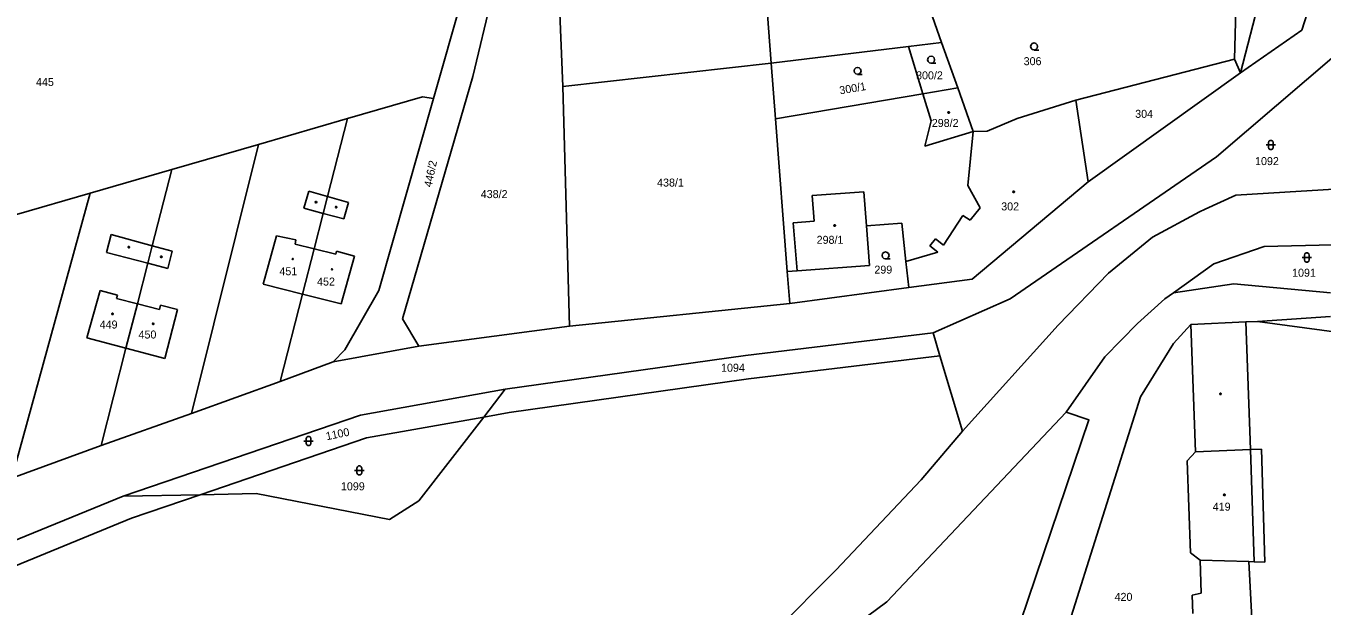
# Model space of a CAD drawing. Extents: x -812394 to -807601, y -1013097 to -1009266.
# Drawn here: x -811273.1 to -810997.7, y -1011712.3 to -1011589.1 of the extents above; entities that cross this region are included whole.
import ezdxf

# ---------------------------------------------------------------- set-up
doc = ezdxf.new("R2010")
doc.units = 0
for name, color, linetype in [('Default', 7, 'Continuous'), ('KN_HRANICE', 7, 'Continuous'), ('KN_KULTURY', 7, 'Continuous'), ('KN_PARCELY', 7, 'Continuous'), ('KN_SLUCKY', 7, 'Continuous')]:
    doc.layers.add(name, color=color, linetype=linetype)

# ---------------------------------------------------------------- blocks, each defined once
blk = doc.blocks.new('304')
at = {"layer": 'Default'}
blk.add_lwpolyline([(0, 0), (-0.38, 0.1), (-0.65, 0.37), (-0.75, 0.74), (-0.65, 1.11), (-0.38, 1.38), (-0.01, 1.48), (0.36, 1.38), (0.63, 1.11), (0.73, 0.73), (0.63, 0.35), (0.36, 0.08), (-0.02, -0.02), (0.98, -0.02)], dxfattribs=at)
blk = doc.blocks.new('316')
at = {"layer": 'Default'}
for points in [[(-1, 1), (0.27, 1), (1, 1)], [(-0.5, 1.5), (-0.4, 1.79), (-0.15, 1.97), (0.16, 1.97), (0.41, 1.79), (0.51, 1.5), (0.51, 0.5), (0.41, 0.21), (0.16, 0.03), (-0.15, 0.03), (-0.4, 0.21), (-0.5, 0.5), (-0.5, 1.5)]]:
    blk.add_lwpolyline(points, dxfattribs=at)
blk = doc.blocks.new('NAHRADNI_SYMBOL')
at = {"layer": 'Default'}
blk.add_lwpolyline([(0.09, 0.15), (0.18, 0), (0.09, -0.15), (-0.09, -0.15), (-0.18, 0), (-0.09, 0.15), (0.09, 0.15)], dxfattribs=at)
blk = doc.blocks.new('402')
at = {"layer": 'Default'}
blk.add_lwpolyline([(0.09, 0.15), (0.18, 0), (0.09, -0.15), (-0.09, -0.15), (-0.18, 0), (-0.09, 0.15), (0.09, 0.15)], dxfattribs=at)

msp = doc.modelspace()

# ---------------------------------------------------------------- linework, layer by layer
at = {"layer": 'KN_HRANICE'}
for p, q in [((-811178.18, -1011599.83), (-811166.46, -1011550.55)), ((-811078.55, -1011592.58), (-811086.24, -1011570.61)), ((-811008.1, -1011572.3), (-811015.03, -1011599.04)), ((-811114.74, -1011597.01), (-811116.42, -1011574.14)), ((-811186.53, -1011604.51), (-811179.22, -1011578.9)), ((-811159.98, -1011578.81), (-811159.05, -1011601.95)), ((-811001.99, -1011589.96), (-810998.41, -1011578.57)), ((-811016.02, -1011585.65), (-811016.27, -1011596.11)), ((-811015.03, -1011599.04), (-811001.99, -1011589.96)), ((-811114.74, -1011597.01), (-811085.57, -1011593.44)), ((-811085.57, -1011593.44), (-811078.55, -1011592.58)), ((-811082.51, -1011603.49), (-811085.57, -1011593.44)), ((-811078.55, -1011592.58), (-811075.12, -1011602.24)), ((-811159.05, -1011601.95), (-811114.74, -1011597.01)), ((-811113.84, -1011608.78), (-811114.74, -1011597.01)), ((-811049.99, -1011604.85), (-811016.27, -1011596.11)), ((-811020.14, -1011616.85), (-810994.59, -1011595.07)), ((-811015.03, -1011599.04), (-811016.27, -1011596.11)), ((-811193.09, -1011651.29), (-811178.18, -1011599.83)), ((-811047.37, -1011622.22), (-811015.03, -1011599.04)), ((-811159.05, -1011601.95), (-811157.58, -1011652.84)), ((-811075.12, -1011602.24), (-811082.51, -1011603.49)), ((-811075.12, -1011602.24), (-811071.83, -1011611.51)), ((-811204.79, -1011608.77), (-811188.82, -1011604.14)), ((-811198.15, -1011645.26), (-811186.53, -1011604.51)), ((-811188.82, -1011604.14), (-811186.53, -1011604.51)), ((-811082.51, -1011603.49), (-811113.84, -1011608.78)), ((-811080.76, -1011609.22), (-811082.51, -1011603.49)), ((-811062.46, -1011608.77), (-811049.99, -1011604.85)), ((-811047.37, -1011622.22), (-811049.99, -1011604.85)), ((-811223.68, -1011614.25), (-811204.79, -1011608.77)), ((-811209.02, -1011625.33), (-811204.79, -1011608.77)), ((-811111.34, -1011641.25), (-811113.84, -1011608.78)), ((-811082.09, -1011614.65), (-811080.76, -1011609.22)), ((-811068.83, -1011611.45), (-811062.46, -1011608.77)), ((-811071.83, -1011611.51), (-811082.09, -1011614.65)), ((-811072.96, -1011622.96), (-811071.83, -1011611.51)), ((-811071.83, -1011611.51), (-811068.83, -1011611.45)), ((-811242.11, -1011619.59), (-811223.68, -1011614.25)), ((-811237.94, -1011671.39), (-811223.68, -1011614.25)), ((-811063.97, -1011647.03), (-811020.14, -1011616.85)), ((-811259.45, -1011624.61), (-811242.11, -1011619.59)), ((-811246.26, -1011635.77), (-811242.11, -1011619.59)), ((-811276.13, -1011685.2), (-811259.45, -1011624.61)), ((-811275.14, -1011629.16), (-811259.45, -1011624.61)), ((-811070.33, -1011627.71), (-811072.96, -1011622.96)), ((-811072.01, -1011642.87), (-811047.37, -1011622.22)), ((-811209.93, -1011628.91), (-811209.02, -1011625.33)), ((-811211.85, -1011636.43), (-811209.93, -1011628.91)), ((-811074.03, -1011629.35), (-811078.1, -1011635.68)), ((-811072.48, -1011630.33), (-811074.03, -1011629.35)), ((-811070.33, -1011627.71), (-811072.48, -1011630.33)), ((-811033.74, -1011633.95), (-811023.75, -1011628.6)), ((-811023.75, -1011628.6), (-811022.52, -1011628.03)), ((-811094.5, -1011631.56), (-811086.99, -1011630.95)), ((-811094.5, -1011631.56), (-811093.86, -1011639.95)), ((-811086.99, -1011630.95), (-811086.11, -1011639.13)), ((-811247.2, -1011639.45), (-811246.26, -1011635.77)), ((-811079.86, -1011634.34), (-811081.05, -1011635.82)), ((-811081.05, -1011635.82), (-811079.35, -1011637.16)), ((-811078.1, -1011635.68), (-811079.86, -1011634.34)), ((-811043.08, -1011641.62), (-811033.74, -1011633.95)), ((-811214.31, -1011646.05), (-811211.85, -1011636.43)), ((-811086.11, -1011639.13), (-811079.35, -1011637.16)), ((-811249.43, -1011648.14), (-811247.2, -1011639.45)), ((-811109.22, -1011641.09), (-811111.34, -1011641.25)), ((-811110.82, -1011648.06), (-811111.34, -1011641.25)), ((-811093.86, -1011639.95), (-811109.22, -1011641.09)), ((-811086.11, -1011639.13), (-811085.52, -1011644.68)), ((-811085.52, -1011644.68), (-811072.01, -1011642.87)), ((-811053.75, -1011652.65), (-811043.08, -1011641.62)), ((-811016.44, -1011643.9), (-811029.29, -1011645.78)), ((-810995.89, -1011645.77), (-811016.44, -1011643.9)), ((-811219.05, -1011664.64), (-811214.31, -1011646.05)), ((-811205.32, -1011657.9), (-811198.15, -1011645.26)), ((-811110.82, -1011648.06), (-811085.52, -1011644.68)), ((-811251.85, -1011657.56), (-811249.43, -1011648.14)), ((-811110.82, -1011648.06), (-811157.58, -1011652.84)), ((-811080.33, -1011654.28), (-811063.97, -1011647.03)), ((-811189.59, -1011657.14), (-811193.09, -1011651.29)), ((-811013.86, -1011651.97), (-811025.55, -1011652.51)), ((-811011.38, -1011651.85), (-811013.86, -1011651.97)), ((-811011.38, -1011651.85), (-810995.89, -1011650.79)), ((-810971.7, -1011657.24), (-811011.38, -1011651.85)), ((-811189.59, -1011657.14), (-811157.58, -1011652.84)), ((-811120.19, -1011659.13), (-811080.33, -1011654.28)), ((-811080.33, -1011654.28), (-811078.89, -1011659.14)), ((-811074.13, -1011675.17), (-811053.75, -1011652.65)), ((-811025.55, -1011652.51), (-811029.28, -1011656.56)), ((-811024.55, -1011679.56), (-811025.55, -1011652.51)), ((-811257.15, -1011678.25), (-811251.85, -1011657.56)), ((-811207.83, -1011660.48), (-811189.59, -1011657.14)), ((-811207.83, -1011660.48), (-811205.32, -1011657.9)), ((-811029.28, -1011656.56), (-811036.27, -1011667.85)), ((-811219.05, -1011664.64), (-811207.83, -1011660.48)), ((-811171.25, -1011666.28), (-811120.19, -1011659.13)), ((-811078.89, -1011659.14), (-811119.54, -1011664.09)), ((-811074.13, -1011675.17), (-811078.89, -1011659.14)), ((-811237.94, -1011671.39), (-811219.05, -1011664.64)), ((-811119.54, -1011664.09), (-811170.46, -1011671.22)), ((-811202.01, -1011671.78), (-811171.25, -1011666.28)), ((-811171.25, -1011666.28), (-811175.83, -1011672.18)), ((-811036.27, -1011667.85), (-811058.25, -1011737.49)), ((-811257.15, -1011678.25), (-811237.94, -1011671.39)), ((-811170.46, -1011671.22), (-811175.83, -1011672.18)), ((-811252.46, -1011689.01), (-811202.01, -1011671.78)), ((-811175.83, -1011672.18), (-811200.75, -1011676.63)), ((-811189.64, -1011689.98), (-811175.83, -1011672.18)), ((-811200.75, -1011676.63), (-811236.06, -1011688.69)), ((-811082.88, -1011685.55), (-811074.13, -1011675.17)), ((-811276.13, -1011685.2), (-811257.15, -1011678.25)), ((-811026.38, -1011681.48), (-811024.55, -1011679.56)), ((-811024.55, -1011679.56), (-811012.93, -1011679.1)), ((-811012.93, -1011679.1), (-811010.59, -1011679.01)), ((-811009.86, -1011703), (-811010.59, -1011679.01)), ((-811025.62, -1011701.03), (-811026.38, -1011681.48)), ((-811101.04, -1011704.72), (-811082.88, -1011685.55)), ((-811305.52, -1011710.63), (-811252.46, -1011689.01)), ((-811236.06, -1011688.69), (-811252.46, -1011689.01)), ((-811236.06, -1011688.69), (-811250.71, -1011693.69)), ((-811236.06, -1011688.69), (-811224.18, -1011688.46)), ((-811224.18, -1011688.46), (-811195.82, -1011693.94)), ((-811195.82, -1011693.94), (-811189.64, -1011689.98)), ((-811250.71, -1011693.69), (-811375.13, -1011744.58)), ((-811025.62, -1011701.03), (-811023.6, -1011702.59)), ((-811113.97, -1011717.72), (-811101.04, -1011704.72)), ((-811023.6, -1011702.59), (-811023.35, -1011709.59)), ((-811023.6, -1011702.59), (-811013.26, -1011702.91)), ((-811013.26, -1011702.91), (-811012.11, -1011702.94)), ((-811012.11, -1011702.94), (-811009.86, -1011703)), ((-811023.35, -1011709.59), (-811025.3, -1011710.01)), ((-811025.3, -1011710.01), (-811025.13, -1011713.95))]:
    msp.add_line(p, q, dxfattribs=at)
for points in [[(-811005.6, -1011624.4), (-811016.01, -1011625.04), (-811022.52, -1011628.03)], [(-810982.75, -1011623.07), (-810983.49, -1011623.04), (-811005.6, -1011624.4)], [(-811029.29, -1011645.78), (-811020.71, -1011639.62), (-811010, -1011635.94), (-810983.72, -1011635.29), (-810982.94, -1011635.34)], [(-811052.04, -1011671.11), (-811043.88, -1011659.38), (-811036.94, -1011652.27), (-811031.09, -1011647.08), (-811029.29, -1011645.78)], [(-811123.04, -1011735.83), (-811090.17, -1011711.42), (-811052.04, -1011671.11)], [(-811074.63, -1011753.78), (-811047.22, -1011672.77), (-811052.04, -1011671.11)]]:
    msp.add_lwpolyline(points, dxfattribs=at)
at = {"layer": 'KN_SLUCKY'}
for p, q in [((-811212.97, -1011624.2), (-811214.03, -1011627.79)), ((-811209.02, -1011625.33), (-811212.97, -1011624.2)), ((-811106.05, -1011625.09), (-811095.06, -1011624.33)), ((-811095.06, -1011624.33), (-811094.5, -1011631.56)), ((-811204.58, -1011626.6), (-811209.02, -1011625.33)), ((-811205.58, -1011630.09), (-811204.58, -1011626.6)), ((-811105.59, -1011630.56), (-811106.05, -1011625.09)), ((-811214.03, -1011627.79), (-811209.93, -1011628.91)), ((-811209.93, -1011628.91), (-811205.58, -1011630.09)), ((-811110.07, -1011630.94), (-811105.59, -1011630.56)), ((-811109.22, -1011641.09), (-811110.07, -1011630.94)), ((-811255.01, -1011633.38), (-811256.02, -1011637.19)), ((-811246.26, -1011635.77), (-811255.01, -1011633.38)), ((-811242.03, -1011636.92), (-811246.26, -1011635.77)), ((-811219.86, -1011633.69), (-811222.71, -1011643.91)), ((-811215.73, -1011634.51), (-811219.86, -1011633.69)), ((-811215.87, -1011635.44), (-811215.73, -1011634.51)), ((-811211.85, -1011636.43), (-811215.87, -1011635.44)), ((-811247.2, -1011639.45), (-811256.02, -1011637.19)), ((-811242.99, -1011640.61), (-811242.03, -1011636.92)), ((-811207.26, -1011637.55), (-811211.85, -1011636.43)), ((-811207.08, -1011636.91), (-811207.26, -1011637.55)), ((-811203.29, -1011637.97), (-811207.08, -1011636.91)), ((-811206.13, -1011648.13), (-811203.29, -1011637.97)), ((-811247.2, -1011639.45), (-811242.99, -1011640.61)), ((-811222.71, -1011643.91), (-811214.31, -1011646.05)), ((-811257.36, -1011645.28), (-811260.18, -1011655.38)), ((-811253.64, -1011646.25), (-811257.36, -1011645.28)), ((-811253.83, -1011646.99), (-811253.64, -1011646.25)), ((-811214.31, -1011646.05), (-811206.13, -1011648.13)), ((-811249.43, -1011648.14), (-811253.83, -1011646.99)), ((-811244.72, -1011649.36), (-811249.43, -1011648.14)), ((-811244.48, -1011648.43), (-811244.72, -1011649.36)), ((-811240.89, -1011649.36), (-811244.48, -1011648.43)), ((-811243.58, -1011659.72), (-811240.89, -1011649.36)), ((-811012.93, -1011679.1), (-811013.86, -1011651.97)), ((-811260.18, -1011655.38), (-811251.85, -1011657.56)), ((-811251.85, -1011657.56), (-811243.58, -1011659.72)), ((-811012.11, -1011702.94), (-811012.93, -1011679.1)), ((-811013.26, -1011702.91), (-811012.49, -1011717.69))]:
    msp.add_line(p, q, dxfattribs=at)

# ---------------------------------------------------------------- block references
at = {"layer": 'KN_KULTURY'}
for name, p in [('304', (-811058.88, -1011594.17)), ('304', (-811080.75, -1011596.98)), ('304', (-811096.38, -1011599.35)), ('NAHRADNI_SYMBOL', (-811077.02, -1011607.45)), ('316', (-811008.57, -1011615.36)), ('NAHRADNI_SYMBOL', (-811063.22, -1011624.33)), ('402', (-811211.46, -1011626.52)), ('402', (-811207.18, -1011627.57)), ('402', (-811101.25, -1011631.5)), ('402', (-811251.25, -1011636.07)), ('402', (-811244.35, -1011638.14)), ('304', (-811090.44, -1011638.56)), ('316', (-811000.94, -1011639.27)), ('402', (-811254.72, -1011650.26)), ('402', (-811246.08, -1011652.35)), ('402', (-811019.27, -1011667.27)), ('316', (-811213.05, -1011678.27)), ('316', (-811202.27, -1011684.52)), ('402', (-811018.44, -1011688.73))]:
    msp.add_blockref(name, p, dxfattribs=at)
at = {"layer": 'KN_KULTURY', "xscale": 0.67, "yscale": 0.67}
for p in [(-811216.41, -1011638.59), (-811208.07, -1011640.78)]:
    msp.add_blockref('402', p, dxfattribs=at)

# ---------------------------------------------------------------- texts
at = {"layer": 'KN_PARCELY'}
for s, p in [('306', (-811061.1, -1011597.41)), ('445', (-811270.97, -1011601.83)), ('300/2', (-811083.96, -1011600.42)), ('304', (-811037.4, -1011608.6)), ('298/2', (-811080.62, -1011610.54)), ('1092', (-811011.93, -1011618.64)), ('438/1', (-811138.99, -1011623.2)), ('438/2', (-811176.46, -1011625.65)), ('302', (-811065.87, -1011628.27)), ('298/1', (-811105.09, -1011635.37)), ('451', (-811219.24, -1011642.05)), ('299', (-811092.82, -1011641.7)), ('1091', (-811004.06, -1011642.36)), ('452', (-811211.24, -1011644.24)), ('449', (-811257.44, -1011653.37)), ('450', (-811249.18, -1011655.49)), ('1094', (-811125.4, -1011662.55)), ('1099', (-811206.17, -1011687.75)), ('419', (-811020.92, -1011692.07)), ('420', (-811041.78, -1011711.24))]:
    msp.add_text(s, height=1.7, dxfattribs=at).set_placement(p)
for s, rotation, p in [('300/1', 9.626, (-811100.1, -1011603.63)), ('446/2', 78.266, (-811186.9, -1011623.43)), ('1100', 11.574, (-811209.2, -1011677.12))]:
    msp.add_text(s, height=1.7, rotation=rotation, dxfattribs=at).set_placement(p)

doc.saveas('drawing.dxf')
